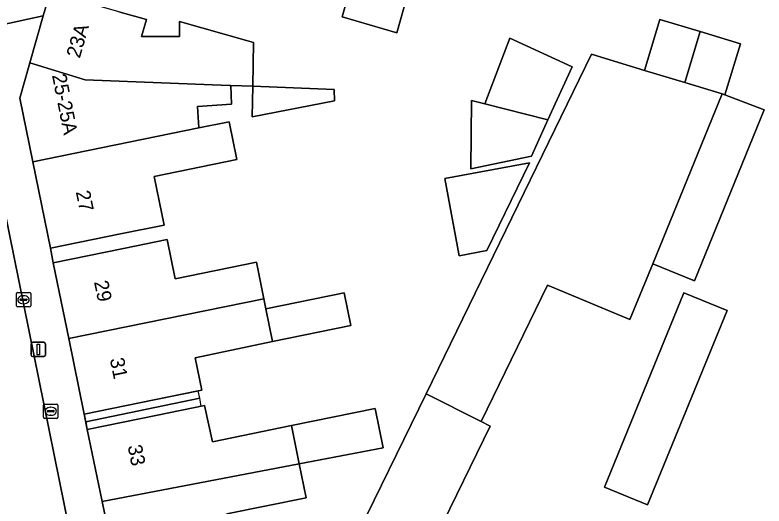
# Model space of a CAD drawing. Extents: x 158086 to 159499, y 382904 to 383981.
# Drawn here: x 158699.2 to 158751.5, y 383180.1 to 383214.5 of the extents above; entities that cross this region are included whole.
import ezdxf

# ---------------------------------------------------------------- set-up
doc = ezdxf.new("R2010")
doc.units = 0
for name, color, linetype in [('IMGEO_Brandkraan', 7, 'Continuous'), ('IMGEO_Erf', 7, 'Continuous'), ('IMGEO_Kolk', 7, 'Continuous'), ('IMGEO_Lichtmast', 7, 'Continuous'), ('IMGEO_Pand', 7, 'Continuous'), ('IMGEO_Pand_nummerreeks', 7, 'Continuous'), ('IMGEO_Pand_overbouw', 7, 'Continuous'), ('IMGEO_Rijbaan_lokaal_open', 7, 'Continuous'), ('IMGEO_Voetpad_open', 7, 'Continuous')]:
    doc.layers.add(name, color=color, linetype=linetype)

msp = doc.modelspace()

# ---------------------------------------------------------------- linework, layer by layer
at = {"layer": 'IMGEO_Brandkraan'}
for p, q in [((158701.168, 383186.329), (158701.168, 383187.181)), ((158701.243, 383187.255), (158702.095, 383187.255)), ((158701.47, 383186.798), (158701.868, 383186.798)), ((158701.656, 383187.035), (158701.681, 383187.035)), ((158702.169, 383187.181), (158702.169, 383186.329)), ((158702.095, 383186.255), (158701.243, 383186.255)), ((158701.427, 383186.749), (158701.427, 383186.761)), ((158701.865, 383186.712), (158701.467, 383186.712)), ((158701.679, 383186.475), (158701.654, 383186.475)), ((158701.911, 383186.761), (158701.911, 383186.749))]:
    msp.add_line(p, q, dxfattribs=at)
for points in [[(158701.168, 383186.329), (158701.168, 383187.181)], [(158701.243, 383187.255), (158702.095, 383187.255)], [(158702.169, 383187.181), (158702.169, 383186.329)], [(158702.095, 383186.255), (158701.243, 383186.255)]]:
    msp.add_lwpolyline(points, dxfattribs=at)
for centre, radius, start, end in [((158701.245, 383187.179), 0.0765, 91.552, 178.448), ((158701.245, 383187.179), 0.0765, 91.552, 178.448), ((158701.467, 383186.758), 0.0403, 85.8775, 175.7526), ((158701.872, 383186.76), 0.0386, 1.7309, 96.639), ((158702.093, 383187.179), 0.0765, 1.552, 88.448), ((158702.093, 383187.179), 0.0765, 1.552, 88.448), ((158701.245, 383186.331), 0.0765, 181.552, 268.448), ((158701.245, 383186.331), 0.0765, 181.552, 268.448), ((158701.464, 383186.748), 0.0366, 178.938, 274.7102), ((158701.868, 383186.755), 0.043, 264.8664, 352.4533), ((158702.093, 383186.331), 0.0765, 271.552, 358.448), ((158702.093, 383186.331), 0.0765, 271.552, 358.448)]:
    msp.add_arc(centre, radius, start, end, dxfattribs=at)
for centre, major_axis, ratio, start_param, end_param in [((158701.655, 383186.755), (-0.387, 0.002), 0.722429, 4.712389, 7.853982), ((158701.68, 383186.755), (-0.39, 0.002), 0.717154, 1.570796, 4.712389)]:
    msp.add_ellipse(centre, major_axis=major_axis, ratio=ratio, start_param=start_param, end_param=end_param, dxfattribs=at)
at = {"layer": 'IMGEO_Erf'}
for points in [[(158725.869, 383213.235), (158722.032, 383214.339), (158722.858, 383217.21), (158726.641, 383215.979)], [(158746.668, 383195.887), (158743.755, 383197.073), (158742.155, 383193.172), (158736.406, 383195.583), (158731.752, 383186.034), (158732.394, 383185.711), (158727.241, 383175.139), (158722.725, 383177.34), (158727.906, 383187.968), (158739.485, 383211.722), (158743.178, 383210.601), (158744.26, 383214.167), (158747.073, 383213.313), (158749.886, 383212.459), (158748.803, 383208.893), (158751.536, 383207.848)], [(158738.122, 383210.843), (158736.43, 383207.138), (158735.274, 383204.607), (158731.029, 383203.702), (158731.085, 383208.491), (158732.015, 383208.256), (158733.761, 383212.857)], [(158715.793, 383209.493), (158721.494, 383209.258), (158721.518, 383208.467), (158715.751, 383207.339)], [(158732.146, 383197.993), (158730.216, 383197.636), (158729.218, 383203.031), (158735.135, 383204.126)], [(158743.393, 383180.217), (158740.377, 383181.451), (158745.935, 383195.043), (158748.951, 383193.81)]]:
    msp.add_lwpolyline(points, close=True, dxfattribs=at)
msp.add_lwpolyline([(158706.434, 383214.704), (158708.359, 383214.151), (158708.02, 383212.967), (158710.665, 383212.979), (158710.66, 383214.025), (158715.348, 383212.692), (158715.852, 383212.549), (158715.793, 383209.493), (158714.265, 383209.539), (158714.294, 383208.238), (158711.922, 383208.066), (158712.021, 383206.574), (158714.137, 383207.008), (158714.678, 383204.368), (158708.905, 383203.184), (158709.602, 383199.782), (158706.547, 383199.162), (158701.648, 383198.157), (158701.845, 383197.131), (158706.744, 383198.133), (158709.811, 383198.76), (158710.373, 383196.014), (158716.047, 383197.174), (158716.567, 383194.629), (158716.713, 383193.913), (158722.176, 383195.031), (158722.641, 383192.756), (158717.179, 383191.638), (158711.765, 383190.5), (158712.228, 383188.237), (158708.906, 383187.557), (158704.007, 383186.555), (158704.225, 383185.487), (158709.124, 383186.488), (158712.423, 383187.162), (158712.967, 383184.62), (158718.497, 383185.75), (158724.35, 383186.946), (158724.911, 383184.197), (158719.044, 383183.076), (158719.529, 383180.702), (158713.981, 383179.571)], dxfattribs=at)
at = {"layer": 'IMGEO_Kolk'}
for p, q in [((158699.265, 383194.128), (158699.265, 383194.98)), ((158699.34, 383195.054), (158700.192, 383195.054)), ((158699.753, 383194.834), (158699.778, 383194.834)), ((158700.266, 383194.98), (158700.266, 383194.128)), ((158699.524, 383194.548), (158699.524, 383194.56)), ((158699.962, 383194.511), (158699.564, 383194.511)), ((158699.567, 383194.597), (158699.965, 383194.597)), ((158699.776, 383194.274), (158699.751, 383194.274)), ((158700.008, 383194.56), (158700.008, 383194.548)), ((158700.192, 383194.054), (158699.34, 383194.054))]:
    msp.add_line(p, q, dxfattribs=at)
for points in [[(158699.265, 383194.128), (158699.265, 383194.98)], [(158699.34, 383195.054), (158700.192, 383195.054)], [(158700.266, 383194.98), (158700.266, 383194.128)], [(158700.192, 383194.054), (158699.34, 383194.054)]]:
    msp.add_lwpolyline(points, dxfattribs=at)
for centre, radius, start, end in [((158699.342, 383194.978), 0.0765, 91.552, 178.448), ((158699.342, 383194.978), 0.0765, 91.552, 178.448), ((158700.19, 383194.978), 0.0765, 1.552, 88.448), ((158700.19, 383194.978), 0.0765, 1.552, 88.448), ((158699.342, 383194.13), 0.0765, 181.552, 268.448), ((158699.342, 383194.13), 0.0765, 181.552, 268.448), ((158699.564, 383194.557), 0.0403, 85.8775, 175.7526), ((158699.561, 383194.547), 0.0366, 178.938, 274.7102), ((158699.965, 383194.554), 0.043, 264.8664, 352.4533), ((158699.969, 383194.559), 0.0386, 1.7309, 96.639), ((158700.19, 383194.13), 0.0765, 271.552, 358.448), ((158700.19, 383194.13), 0.0765, 271.552, 358.448)]:
    msp.add_arc(centre, radius, start, end, dxfattribs=at)
for centre, major_axis, ratio, start_param, end_param in [((158699.752, 383194.554), (-0.387, 0.002), 0.722429, 4.712389, 7.853982), ((158699.777, 383194.554), (-0.39, 0.002), 0.717154, 1.570796, 4.712389)]:
    msp.add_ellipse(centre, major_axis=major_axis, ratio=ratio, start_param=start_param, end_param=end_param, dxfattribs=at)
at = {"layer": 'IMGEO_Lichtmast'}
for p, q in [((158700.404, 383191.576), (158701.194, 383191.576)), ((158701.194, 383191.576), (158700.404, 383191.576)), ((158700.304, 383190.676), (158700.304, 383191.476)), ((158700.304, 383191.476), (158700.304, 383190.676)), ((158701.294, 383191.476), (158701.294, 383190.676)), ((158701.294, 383190.676), (158701.294, 383191.476)), ((158701.194, 383190.576), (158700.404, 383190.576)), ((158700.404, 383190.576), (158701.194, 383190.576))]:
    msp.add_line(p, q, dxfattribs=at)
msp.add_lwpolyline([(158700.724, 383191.451), (158700.874, 383191.451), (158700.874, 383190.701), (158700.724, 383190.701), (158700.724, 383191.451)], dxfattribs=at)
for centre, start, end in [((158700.404, 383191.476), 90, 180), ((158700.404, 383191.476), 90, 180), ((158701.194, 383191.476), 0, 90), ((158701.194, 383191.476), 360, 90), ((158700.404, 383190.676), 180, 270), ((158700.404, 383190.676), 180, 270), ((158701.194, 383190.676), 270, 0), ((158701.194, 383190.676), 270, 0)]:
    msp.add_arc(centre, 0.1, start, end, dxfattribs=at)
at = {"layer": 'IMGEO_Pand'}
for points in [[(158726.641, 383215.979), (158722.858, 383217.21), (158722.032, 383214.339), (158725.869, 383213.235)], [(158700.205, 383211.127), (158704.086, 383209.931), (158714.155, 383209.543), (158714.265, 383209.539), (158715.793, 383209.493), (158715.852, 383212.549), (158715.348, 383212.692), (158710.66, 383214.025), (158710.665, 383212.979), (158708.02, 383212.967), (158708.359, 383214.151), (158706.434, 383214.704), (158701.628, 383216.083), (158701.147, 383214.409)], [(158747.073, 383213.313), (158744.26, 383214.167), (158743.178, 383210.601), (158745.99, 383209.747)], [(158747.073, 383213.313), (158745.99, 383209.747), (158748.621, 383208.948), (158748.803, 383208.893), (158749.886, 383212.459)], [(158738.122, 383210.843), (158733.761, 383212.857), (158732.015, 383208.256), (158736.43, 383207.138)], [(158748.621, 383208.948), (158745.99, 383209.747), (158743.178, 383210.601), (158739.485, 383211.722), (158727.906, 383187.968), (158731.752, 383186.034), (158736.406, 383195.583), (158742.155, 383193.172), (158743.755, 383197.073)], [(158700.205, 383211.127), (158699.496, 383208.659), (158700.411, 383204.192), (158712.021, 383206.574), (158711.922, 383208.066), (158714.294, 383208.238), (158714.265, 383209.539), (158714.155, 383209.543), (158704.086, 383209.931)], [(158715.751, 383207.339), (158721.518, 383208.467), (158721.494, 383209.258), (158715.793, 383209.493)], [(158751.536, 383207.848), (158748.803, 383208.893), (158748.621, 383208.948), (158743.755, 383197.073), (158746.668, 383195.887)], [(158736.43, 383207.138), (158732.015, 383208.256), (158731.085, 383208.491), (158731.029, 383203.702), (158735.274, 383204.607)], [(158714.678, 383204.368), (158714.137, 383207.008), (158712.021, 383206.574), (158700.411, 383204.192), (158701.648, 383198.157), (158706.547, 383199.162), (158709.602, 383199.782), (158708.905, 383203.184)], [(158730.216, 383197.636), (158732.146, 383197.993), (158735.135, 383204.126), (158729.218, 383203.031)], [(158702.926, 383191.842), (158716.567, 383194.629), (158716.047, 383197.174), (158710.373, 383196.014), (158709.811, 383198.76), (158706.744, 383198.133), (158701.845, 383197.131)], [(158711.765, 383190.5), (158717.179, 383191.638), (158716.713, 383193.913), (158716.567, 383194.629), (158702.926, 383191.842), (158704.007, 383186.555), (158708.906, 383187.557), (158712.228, 383188.237)], [(158716.713, 383193.913), (158717.179, 383191.638), (158722.641, 383192.756), (158722.176, 383195.031)], [(158748.951, 383193.81), (158745.935, 383195.043), (158740.377, 383181.451), (158743.393, 383180.217)], [(158731.752, 383186.034), (158727.906, 383187.968), (158722.725, 383177.34), (158727.241, 383175.139), (158732.394, 383185.711)], [(158705.257, 383180.441), (158719.044, 383183.076), (158718.497, 383185.75), (158712.967, 383184.62), (158712.423, 383187.162), (158709.124, 383186.488), (158704.225, 383185.487)], [(158718.497, 383185.75), (158719.044, 383183.076), (158724.911, 383184.197), (158724.35, 383186.946)], [(158719.044, 383183.076), (158705.257, 383180.441), (158706.254, 383175.562), (158714.125, 383177.161), (158714.46, 383177.23), (158713.981, 383179.571), (158719.529, 383180.702)]]:
    msp.add_lwpolyline(points, close=True, dxfattribs=at)
at = {"layer": 'IMGEO_Pand_overbouw'}
for points in [[(158712.08, 383187.67), (158711.974, 383188.185), (158708.906, 383187.557), (158704.007, 383186.555), (158704.116, 383186.021)], [(158712.195, 383187.115), (158712.08, 383187.67), (158704.116, 383186.021), (158704.225, 383185.487), (158709.124, 383186.488)]]:
    msp.add_lwpolyline(points, close=True, dxfattribs=at)
at = {"layer": 'IMGEO_Rijbaan_lokaal_open'}
for points in [[(158701.931, 383217.237), (158699.902, 383217.811), (158695.095, 383219.157), (158684.36, 383222.181), (158686.648, 383211.354), (158689.197, 383211.896), (158695.863, 383213.28), (158701.147, 383214.409), (158701.628, 383216.083), (158701.866, 383217.005)], [(158694.56, 383185.406), (158695.407, 383181.511), (158695.954, 383178.787), (158696.63, 383175.421), (158697.565, 383170.765), (158700.485, 383156.696), (158701.263, 383152.874), (158707.882, 383154.298), (158707.173, 383157.706), (158696.271, 383211.43), (158689.571, 383210.062), (158689.821, 383208.876), (158691.34, 383201.679), (158691.468, 383201.079), (158693.192, 383191.692), (158693.424, 383190.625)]]:
    msp.add_lwpolyline(points, close=True, dxfattribs=at)
at = {"layer": 'IMGEO_Voetpad_open'}
msp.add_lwpolyline([(158706.477, 383174.475), (158706.367, 383175.014), (158706.254, 383175.562), (158705.257, 383180.441), (158704.225, 383185.487), (158704.007, 383186.555), (158702.926, 383191.842), (158701.845, 383197.131), (158701.648, 383198.157), (158700.411, 383204.192), (158699.496, 383208.659), (158700.205, 383211.127), (158701.147, 383214.409), (158695.863, 383213.28), (158696.271, 383211.43), (158707.173, 383157.706), (158707.882, 383154.298), (158708.33, 383152.086), (158710.789, 383152.815), (158707.522, 383169.226)], close=True, dxfattribs=at)

# ---------------------------------------------------------------- texts
at = {"layer": 'IMGEO_Pand_nummerreeks'}
for s, rotation, p in [('23A', 73.9798, (158703.695, 383211.396)), ('25-25A', 281.1396, (158701.752, 383210.261)), ('27', 281.5793, (158703.413, 383202.098)), ('29', 281.5535, (158704.689, 383195.801)), ('31', 281.5563, (158705.793, 383190.403)), ('33', 281.5537, (158707.036, 383184.317))]:
    msp.add_text(s, height=1, rotation=rotation, dxfattribs=at).set_placement(p)

doc.saveas('drawing.dxf')
